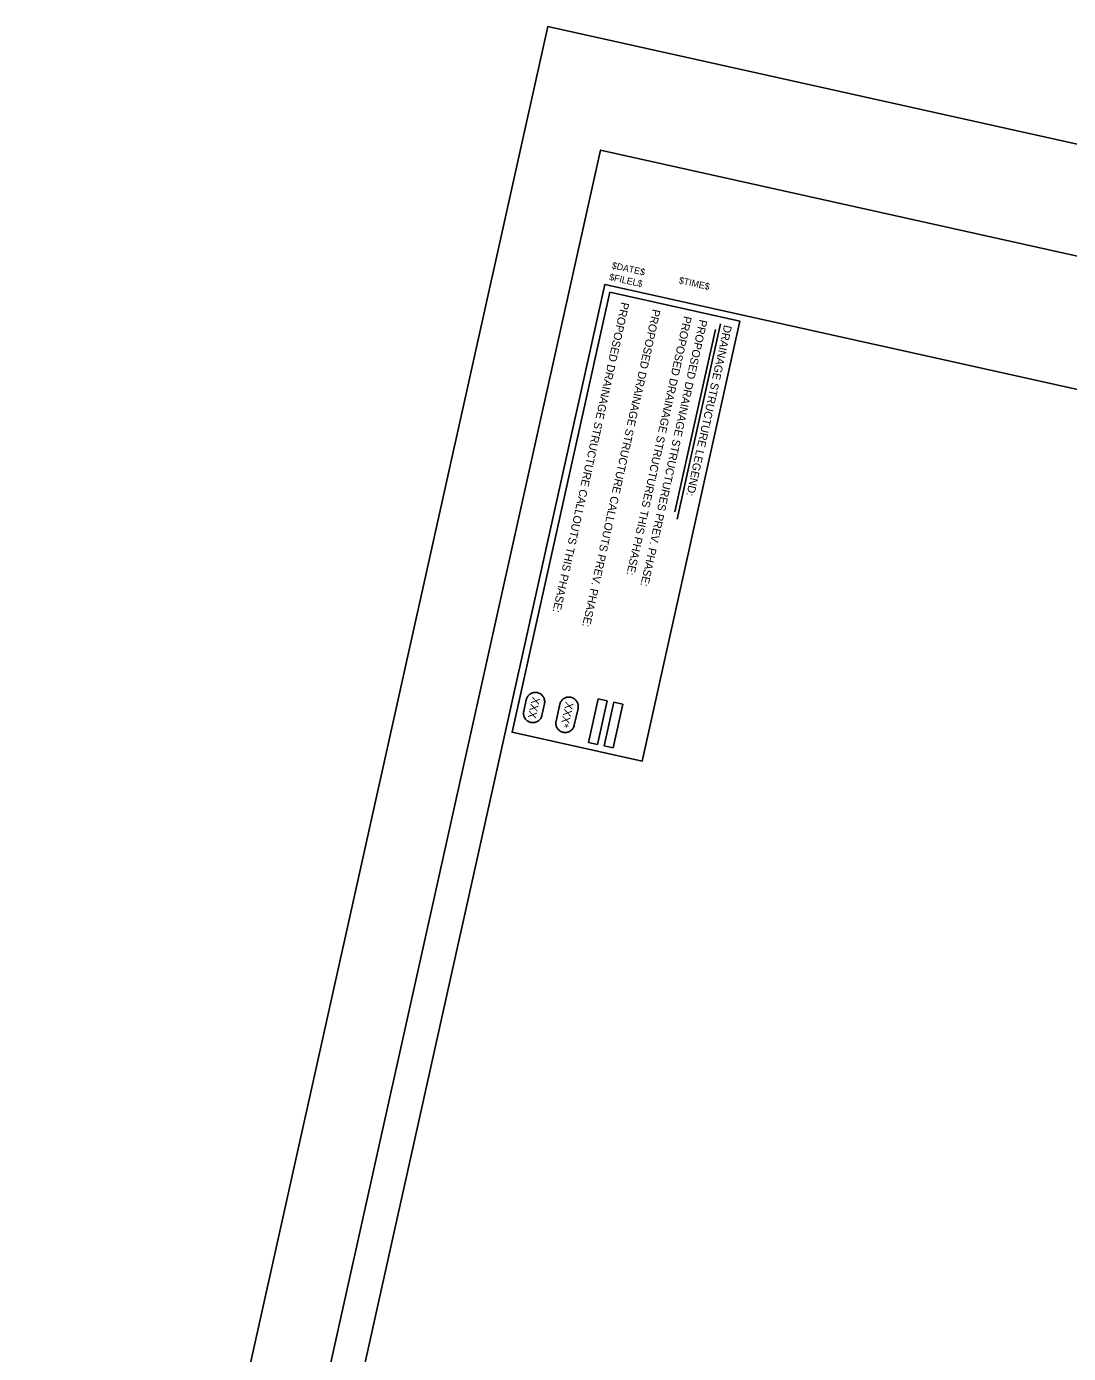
# Model space of a CAD drawing. Extents: x 2149887 to 2151449, y 143603 to 146901.
# Drawn here: x 2149887 to 2150668, y 145906 to 146901 of the extents above; entities that cross this region are included whole.
import ezdxf

# ---------------------------------------------------------------- set-up
doc = ezdxf.new("R2010")
doc.units = 0
for name, color, linetype in [('PR_Storm_Conc_Pipe', 7, 'Continuous'), ('PR_Storm_Conc_Pipe_PH1B', 7, 'Continuous'), ('PR_Storm_Txt', 7, 'Continuous'), ('PR_Storm_Txt_PH1B', 7, 'Continuous'), ('SHT_Plot_Shape_Full', 7, 'Continuous'), ('SHT_Plot_Shape_Half', 7, 'Continuous'), ('SHT_Plot_Stamp', 7, 'Continuous'), ('SHT_Sheet_Border', 7, 'Continuous')]:
    doc.layers.add(name, color=color, linetype=linetype)

msp = doc.modelspace()

# ---------------------------------------------------------------- linework, layer by layer
at = {"layer": 'PR_Storm_Conc_Pipe'}
for p, q in [((2150315.57, 146396.74), (2150308.3, 146364.03)), ((2150315.1, 146362.51), (2150322.38, 146395.23)), ((2150322.38, 146395.23), (2150315.57, 146396.74)), ((2150315.1, 146362.51), (2150308.3, 146364.03))]:
    msp.add_line(p, q, dxfattribs=at)
at = {"layer": 'PR_Storm_Conc_Pipe_PH1B'}
for p, q in [((2150327.28, 146394.13), (2150320.01, 146361.42)), ((2150326.82, 146359.91), (2150334.09, 146392.62)), ((2150334.09, 146392.62), (2150327.28, 146394.13)), ((2150326.82, 146359.91), (2150320.01, 146361.42))]:
    msp.add_line(p, q, dxfattribs=at)
at = {"layer": 'PR_Storm_Txt'}
for p, q in [((2150403.53, 146673.66), (2150373.12, 146536.92)), ((2150407.31, 146677.94), (2150374.73, 146531.44))]:
    msp.add_line(p, q, dxfattribs=at)
msp.add_lwpolyline([(2150421.91, 146679.82), (2150348.56, 146349.95), (2150251.07, 146371.63), (2150324.42, 146701.5)], close=True, dxfattribs=at)
for points in [[(2150261.71, 146396.06), (2150261.87, 146396.65), (2150262.08, 146397.23), (2150262.34, 146397.78), (2150262.64, 146398.31), (2150263, 146398.81), (2150263.39, 146399.28), (2150263.82, 146399.71), (2150264.29, 146400.1), (2150264.79, 146400.45), (2150265.32, 146400.76), (2150265.87, 146401.01), (2150266.45, 146401.22), (2150267.04, 146401.38), (2150267.64, 146401.49), (2150268.24, 146401.54), (2150268.86, 146401.54), (2150269.46, 146401.48), (2150270.07, 146401.38), (2150270.07, 146401.38), (2150270.66, 146401.22), (2150271.23, 146401.01), (2150271.78, 146400.75), (2150272.31, 146400.45), (2150272.81, 146400.1), (2150273.28, 146399.7), (2150273.71, 146399.27), (2150274.1, 146398.8), (2150274.45, 146398.3), (2150274.76, 146397.77), (2150275.01, 146397.22), (2150275.22, 146396.65), (2150275.38, 146396.06), (2150275.49, 146395.45), (2150275.54, 146394.85), (2150275.54, 146394.24), (2150275.49, 146393.63), (2150275.38, 146393.03)], [(2150259.78, 146387.36), (2150261.71, 146396.06)], [(2150275.38, 146393.03), (2150273.44, 146384.32)], [(2150273.44, 146384.32), (2150273.28, 146383.73), (2150273.07, 146383.15), (2150272.82, 146382.6), (2150272.51, 146382.07), (2150272.16, 146381.57), (2150271.77, 146381.1), (2150271.34, 146380.67), (2150270.87, 146380.28), (2150270.37, 146379.93), (2150269.84, 146379.63), (2150269.28, 146379.37), (2150268.71, 146379.16), (2150268.12, 146379), (2150267.52, 146378.9), (2150266.91, 146378.84), (2150266.3, 146378.84), (2150265.69, 146378.9), (2150265.09, 146379), (2150265.09, 146379), (2150264.5, 146379.16), (2150263.93, 146379.37), (2150263.37, 146379.63), (2150262.84, 146379.94), (2150262.34, 146380.29), (2150261.88, 146380.68), (2150261.45, 146381.11), (2150261.05, 146381.58), (2150260.7, 146382.08), (2150260.4, 146382.61), (2150260.14, 146383.16), (2150259.93, 146383.74), (2150259.77, 146384.33), (2150259.67, 146384.93), (2150259.62, 146385.54), (2150259.62, 146386.15), (2150259.67, 146386.75), (2150259.78, 146387.36)]]:
    msp.add_lwpolyline(points, dxfattribs=at)
at = {"layer": 'PR_Storm_Txt_PH1B'}
for points in [[(2150284.04, 146379.97), (2150286.85, 146392.58)], [(2150286.85, 146392.58), (2150287.01, 146393.17), (2150287.22, 146393.74), (2150287.47, 146394.3), (2150287.78, 146394.82), (2150288.13, 146395.32), (2150288.52, 146395.79), (2150288.96, 146396.22), (2150289.42, 146396.62), (2150289.92, 146396.97), (2150290.45, 146397.27), (2150291.01, 146397.53), (2150291.58, 146397.74), (2150292.17, 146397.89), (2150292.77, 146398), (2150293.38, 146398.05), (2150293.99, 146398.05), (2150294.6, 146398), (2150295.2, 146397.89), (2150295.2, 146397.89), (2150295.79, 146397.73), (2150296.36, 146397.52), (2150296.92, 146397.27), (2150297.45, 146396.96), (2150297.95, 146396.61), (2150298.41, 146396.22), (2150298.85, 146395.79), (2150299.24, 146395.32), (2150299.59, 146394.82), (2150299.89, 146394.29), (2150300.15, 146393.73), (2150300.36, 146393.16), (2150300.52, 146392.57), (2150300.62, 146391.97), (2150300.67, 146391.36), (2150300.67, 146390.75), (2150300.62, 146390.14), (2150300.51, 146389.54)], [(2150300.51, 146389.54), (2150297.71, 146376.93)], [(2150297.71, 146376.93), (2150297.55, 146376.34), (2150297.34, 146375.76), (2150297.08, 146375.21), (2150296.78, 146374.68), (2150296.43, 146374.18), (2150296.03, 146373.71), (2150295.6, 146373.28), (2150295.13, 146372.89), (2150294.63, 146372.54), (2150294.1, 146372.24), (2150293.55, 146371.98), (2150292.98, 146371.77), (2150292.39, 146371.61), (2150291.79, 146371.51), (2150291.18, 146371.45), (2150290.57, 146371.45), (2150289.96, 146371.51), (2150289.36, 146371.61), (2150289.36, 146371.61), (2150288.77, 146371.77), (2150288.19, 146371.98), (2150287.64, 146372.24), (2150287.11, 146372.54), (2150286.61, 146372.9), (2150286.14, 146373.29), (2150285.71, 146373.72), (2150285.32, 146374.19), (2150284.97, 146374.69), (2150284.67, 146375.22), (2150284.41, 146375.77), (2150284.2, 146376.35), (2150284.04, 146376.94), (2150283.94, 146377.54), (2150283.88, 146378.15), (2150283.88, 146378.76), (2150283.94, 146379.36), (2150284.04, 146379.97)]]:
    msp.add_lwpolyline(points, dxfattribs=at)
at = {"layer": 'SHT_Plot_Shape_Full'}
msp.add_lwpolyline([(2151449.2, 146640.27), (2151058.5, 144883.19), (2149887.11, 145143.65), (2150277.81, 146900.74)], close=True, dxfattribs=at)
at = {"layer": 'SHT_Plot_Shape_Half'}
msp.add_lwpolyline([(2151391.16, 146569.3), (2151022.16, 144909.83), (2149948.39, 145148.59), (2150317.38, 146808.06)], close=True, dxfattribs=at)
at = {"layer": 'SHT_Sheet_Border'}
msp.add_lwpolyline([(2149978.76, 145170.01), (2150320.63, 146707.46), (2151345.59, 146479.55), (2151003.73, 144942.1)], close=True, dxfattribs=at)

# ---------------------------------------------------------------- texts
at = {"layer": 'PR_Storm_Txt'}
for s, p in [('PROPOSED DRAINAGE STRUCTURE CALLOUTS THIS PHASE:', (2150333.09, 146694.45)), ('PROPOSED DRAINAGE STRUCTURE CALLOUTS PREV. PHASE:', (2150356.52, 146689.24)), ('PROPOSED DRAINAGE STRUCTURES THIS PHASE:', (2150379.95, 146684.03)), ('PROPOSED DRAINAGE STRUCTURES PREV. PHASE:', (2150391.66, 146681.42)), ('DRAINAGE STRUCTURE LEGEND:', (2150410.08, 146677.33)), ('XXX', (2150266.36, 146398.52))]:
    msp.add_text(s, height=6, rotation=257.46382, dxfattribs=at).set_placement(p)
at = {"layer": 'PR_Storm_Txt_PH1B'}
msp.add_text('XXX*', height=6, rotation=257.46382, dxfattribs=at).set_placement((2150291.41, 146394.68))
at = {"layer": 'SHT_Plot_Stamp'}
for s, p in [('$DATE$', (2150325.46, 146719.44)), ('$FILEL$', (2150323.54, 146710.78)), ('$TIME$', (2150375.73, 146708.26))]:
    msp.add_text(s, height=5, rotation=347.46382, dxfattribs=at).set_placement(p)

doc.saveas('drawing.dxf')
